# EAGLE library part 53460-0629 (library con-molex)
IEEE 1394 Firewire Connector 6P 2.0 I/O SOCKET RIGHT-ANGLE UPRIGHT WITH KINK Source: 53460-0629.pdf also DWG.NO. SD-53460-0621
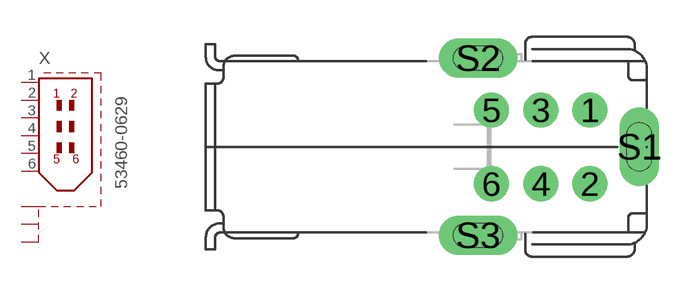
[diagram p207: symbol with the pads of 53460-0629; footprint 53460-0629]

Designator prefix X

## 53460-0629 (MF: MOLEX; MPN: 53460-0629; OC_FARNELL: unknown; OC_NEWARK: 84K7541)  [53460-0629]
1  1  pas
2  2  pas
3  3  pas
4  4  pas
5  5  pas
6  6  pas
S1  S1  pas
S2  S2  pas
S3  S3  pas

## Footprint 53460-0629 (pad centres in mm)
IEEE 1394 Firewire Connector 6P 2.0 I/O SOCKET RIGHT-ANGLE UPRIGHT WITH KINK Source: 53460-0629.pdf also DWG.NO. SD-53460-0621
drill 0.8 pad 1.422 round: 1 2,1.5; 2 2,-1.5; 3 0,1.5; 4 0,-1.5; 5 -2,1.5; 6 -2,-1.5
drill 1 pad 1.6 long: S1 4,0; S2 -2.55,3.6; S3 -2.55,-3.6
